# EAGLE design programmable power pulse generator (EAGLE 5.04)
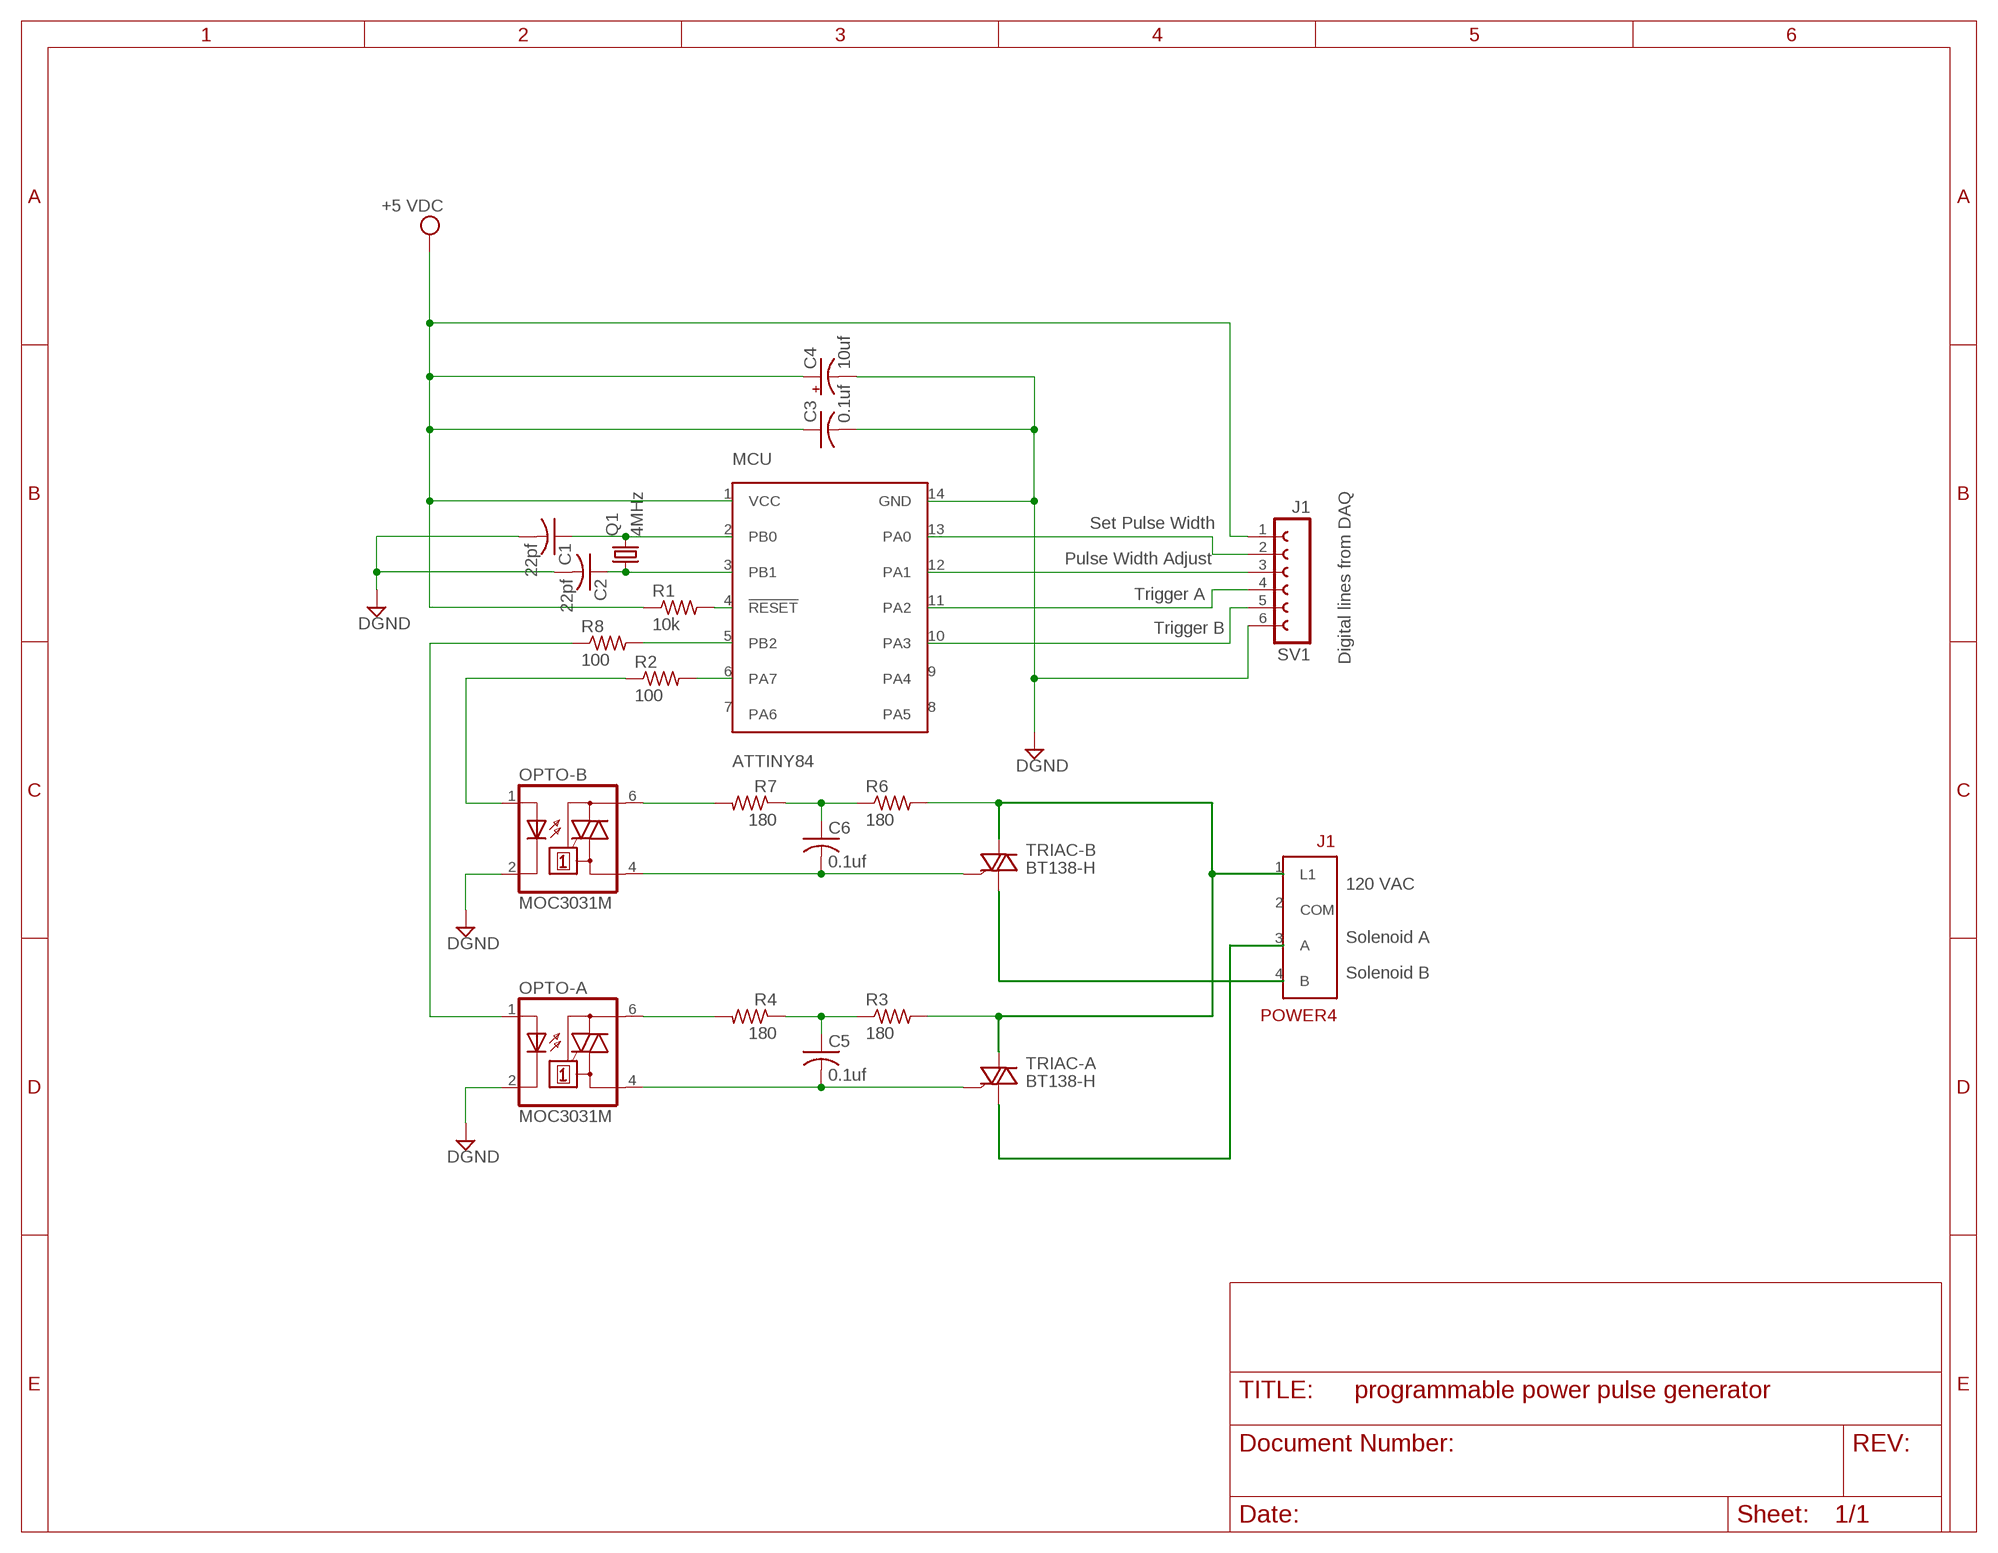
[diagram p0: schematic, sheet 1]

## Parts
C1  22pf  C-US050-035X075  [C050-035X075]
C2  22pf  C-US050-035X075  [C050-035X075]
C3  0.1uf  C-US050-035X075  [C050-035X075]
C4  10uf  CPOL-USE5-5  [E5-5]
C5  0.1uf  C-US050-035X075  [C050-035X075]
C6  0.1uf  C-US050-035X075  [C050-035X075]
J1  POWER4  [POWER4]
MCU  ATTINY84  [DIP14A]
OPTO-A  MOC3031M  [DIL06]
OPTO-B  MOC3031M  [DIL06]
Q1  4MHz  CRYSTALHC49U70  [HC49U70]
R1  10k  R-US_0204/5  [0204/5]
R2  100  R-US_0204/5  [0204/5]
R3  180  R-US_0204/5  [0204/5]
R4  180  R-US_0204/5  [0204/5]
R6  180  R-US_0204/5  [0204/5]
R7  180  R-US_0204/5  [0204/5]
R8  100  R-US_0204/5  [0204/5]
SV1  J1  FE06W  [FE06W]
TRIAC-A  BT138-H  [TO220BH]
TRIAC-B  BT138-H  [TO220BH]

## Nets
AGND: C1.2 C2.2 C3.2 C4.- MCU.14(GND) OPTO-A.2(C) OPTO-B.2(C) SV1.6 ; supply symbol labelled DGND
N$1: MCU.4(!RESET) R1.2
N$2: MCU.5(PB2) R8.2
N$3: MCU.6(PA7) R2.2
N$4: OPTO-B.1(A) R2.1
N$5: OPTO-B.6(A2) R7.2
N$6: C6.1 R6.1 R7.1
N$7: J1.1(L1) R3.2 R6.2 TRIAC-A.T2(A2) TRIAC-B.T2(A2)
N$8: MCU.13(PA0) SV1.2
N$9: C1.1 MCU.2(PB0) Q1.2
N$10: C6.2 OPTO-B.4(A1) TRIAC-B.G
N$11: MCU.12(PA1) SV1.3
N$12: J1.4(B) TRIAC-B.T1(A1)
N$13: OPTO-A.1(A) R8.1
N$14: OPTO-A.6(A2) R4.2
N$15: C5.1 R3.1 R4.1
N$16: J1.3(A) TRIAC-A.T1(A1)
N$17: C5.2 OPTO-A.4(A1) TRIAC-A.G
N$18: MCU.11(PA2) SV1.4
N$21: MCU.10(PA3) SV1.5
N$22: C2.1 MCU.3(PB1) Q1.1
VCC: C3.1 C4.+ MCU.1(VCC) R1.1 SV1.1 ; supply symbol labelled +5 VDC
Unconnected: J1.2(COM) MCU.7(PA6) MCU.8(PA5) MCU.9(PA4)

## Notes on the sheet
- Set Pulse Width
- Pulse Width Adjust
- Trigger A
- Trigger B
- Digital lines from DAQ
- 120 VAC
- Solenoid A
- Solenoid B

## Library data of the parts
C1-C3 C5 C6 = rcl:C-US: CAPACITOR, American symbol
C4 = rcl:CPOL-US: POLARIZED CAPACITOR, American symbol
J1 = trl:POWER4
MCU = trl:ATTINY84: Atmel ATTINY84 MCU, 14DIP
OPTO-A OPTO-B = optocoupler:MOC30*: 6-Pin DIP Zero-Cross Optoisolators Triac Driver Output (250/400 Volt Peak) Source: http://www.fairchildsemi.com/ds/MO/MOC3043-M.pdf
Q1 = crystal:CRYSTAL: CRYSTAL
R1-R4 R6-R8 = resistor:R-US_: RESISTOR, American symbol
SV1 = con-lsta:FE06W: FEMALE HEADER
TRIAC-A TRIAC-B = triac:BT138: TRIAC Source: http://www.semiconductors.philips.com BT138_SERIES_2.pdf

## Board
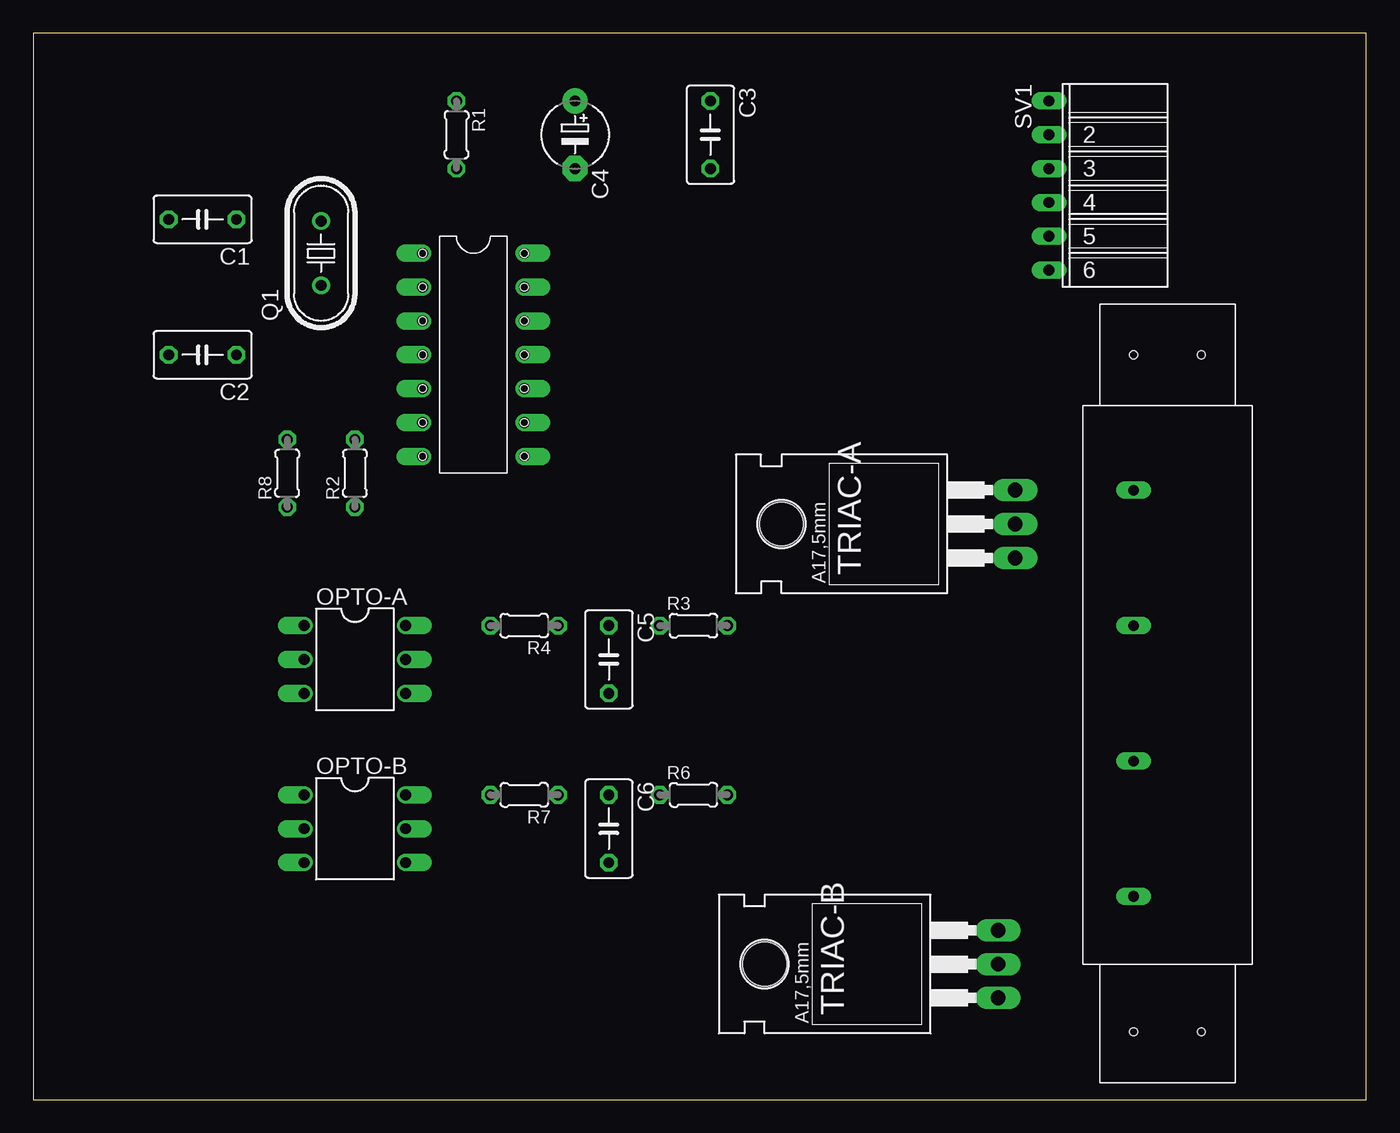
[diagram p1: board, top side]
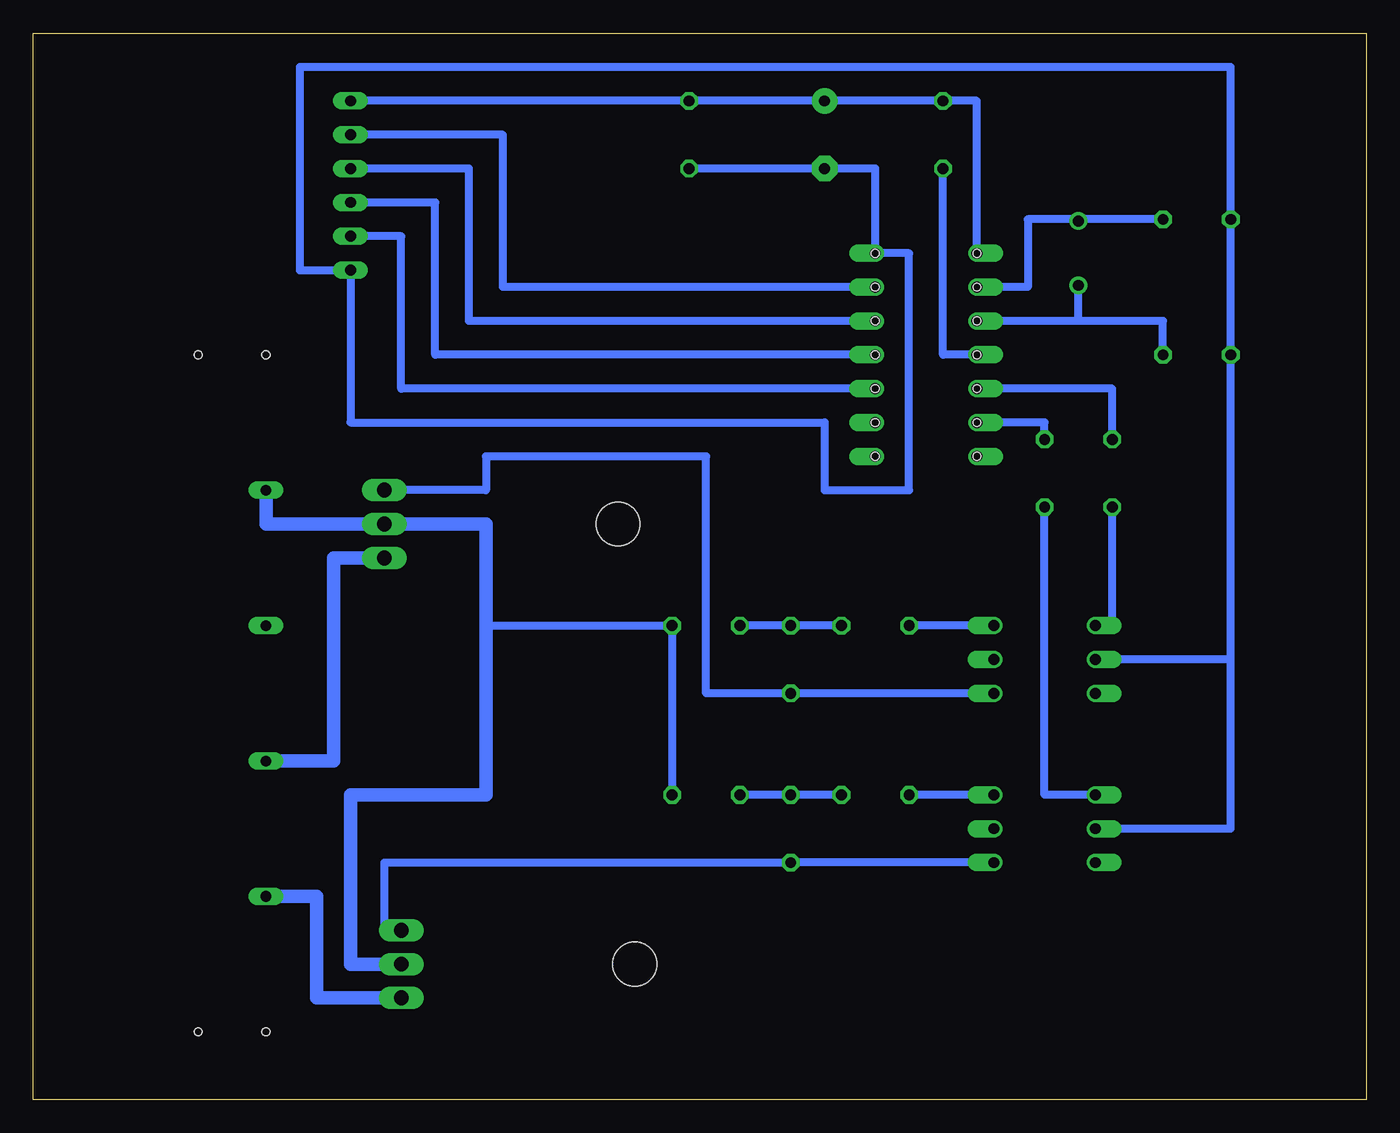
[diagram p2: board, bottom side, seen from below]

Size 100 x 80 mm. Coordinates in mm from the lower left corner, seen from the top.
Outline: 0,0 100,0 100,80 0,80 0,0
Copper layers (1*16): Top 0.035mm / dielectric 1.5mm / Bottom 0.035mm
Design rules "default": minimum track width 10mil, minimum drill 24mil, track to track 8mil, track to pad 8mil, pad to pad 8mil, via to via 8mil, smd to smd 8mil, copper to edge 40mil, drill to drill 8mil, minimum pad ring 10mil, minimum via ring 8mil, stop-mask expansion 4mil, vias tented up to drill 0mil, thermal gap 10mil

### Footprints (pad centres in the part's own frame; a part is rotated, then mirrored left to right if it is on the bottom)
C050-035X075 = drill 0.813 octagon: 1 -2.54,0; 2 2.54,0
E5-5 = drill 0.813 pad 1.905 round: + -2.54,0 | drill 0.813 pad 1.905 octagon: - 2.54,0
POWER4 = drill 0.8 long: 1 1.27,8.89; 2 1.27,-1.27; 3 1.27,-11.43; 4 1.27,-21.59 | hole 0.6: 1.27,19.05; 1.27,-31.75; 6.35,19.05; 6.35,-31.75
DIP14A = drill 0.8 offset: 1 -3.81,8.89; 2 -3.81,6.35; 3 -3.81,3.81; 4 -3.81,1.27; 5 -3.81,-1.27; 6 -3.81,-3.81; 7 -3.81,-6.35; 8 3.81,-6.35; 9 3.81,-3.81; 10 3.81,-1.27; 11 3.81,1.27; 12 3.81,3.81; 13 3.81,6.35; 14 3.81,8.89 | hole 0.6: -3.81,-6.35; -3.81,-3.81; -3.81,-1.27; -3.81,1.27; -3.81,3.81; -3.81,6.35; -3.81,8.89; 3.81,8.89; 3.81,6.35; 3.81,3.81; 3.81,1.27; 3.81,-1.27; 3.81,-3.81; 3.81,-6.35
DIL06 = drill 0.813 offset: 1 -2.54,-3.81; 2 0,-3.81; 3 2.54,-3.81; 4 2.54,3.81; 5 0,3.81; 6 -2.54,3.81
HC49U70 = drill 0.813 round: 1 -2.413,0; 2 2.413,0
0204/5 = drill 0.813 octagon: 1 -2.54,0; 2 2.54,0
FE06W = drill 0.813 long: 1 -6.35,0; 2 -3.81,0; 3 -1.27,0; 4 1.27,0; 5 3.81,0; 6 6.35,0
TO220BH = drill 1.118 long: G 2.54,-6.35; T1 -2.54,-6.35; T2 0,-6.35 | hole 3.302: 0,11.176

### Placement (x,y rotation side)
C1  12.7,66.04 180 top
C2  12.7,55.88 180 top
C3  50.8,72.39 270 top
C4  40.64,72.39 270 top
C5  43.18,33.02 270 top
C6  43.18,20.32 270 top
J1  81.28,36.83 0 top
MCU  33.02,54.61 0 top
OPTO-A  24.13,33.02 270 top
OPTO-B  24.13,20.32 270 top
Q1  21.59,63.5 90 top
R1  31.75,72.39 270 top
R2  24.13,46.99 90 top
R3  49.53,35.56 0 top
R4  36.83,35.56 180 top
R6  49.53,22.86 0 top
R7  36.83,22.86 180 top
R8  19.05,46.99 90 top
SV1  76.2,68.58 270 top
TRIAC-A  67.31,43.18 90 top
TRIAC-B  66.04,10.16 90 top

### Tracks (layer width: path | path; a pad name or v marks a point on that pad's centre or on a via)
AGND
  Bottom 0.61: C3.2 C4.- 36.83,69.85 MCU.14 34.29,63.5 34.29,45.72 40.64,45.72 40.64,50.8 76.2,50.8 SV1.6 80.01,62.23 80.01,77.47 10.16,77.47 C1.2 C2.2 10.16,33.02 | 10.16,33.02 OPTO-A.2 | OPTO-B.2 10.16,20.32 10.16,33.02
N$1
  Bottom 0.61: R1.2 31.75,55.88 MCU.4
N$2
  Bottom 0.61: R8.2 19.05,53.34 MCU.5
N$3
  Bottom 0.61: R2.2 24.13,50.8 MCU.6
N$4
  Bottom 0.61: R2.1 24.13,22.86 OPTO-B.1
N$5
  Bottom 0.61: OPTO-B.6 R7.2
N$6
  Bottom 0.61: R7.1 C6.1 R6.1
N$7
  Bottom 0.61: 66.04,35.56 R3.2 R6.2
  Bottom 1.016: J1.1 82.55,43.18 TRIAC-A.T2 66.04,43.18 66.04,35.56 66.04,22.86 76.2,22.86 76.2,10.16 TRIAC-B.T2
N$8
  Bottom 0.61: MCU.13 64.77,60.96 64.77,72.39 SV1.2
N$9
  Bottom 0.406: 21.59,66.04 Q1.2
  Bottom 0.61: C1.1 21.59,66.04 25.4,66.04 25.4,60.96 MCU.2
N$10
  Bottom 0.61: OPTO-B.4 C6.2 73.66,17.78 73.66,12.7 TRIAC-B.G
N$11
  Bottom 0.61: MCU.12 67.31,58.42 67.31,69.85 SV1.3
N$12
  Bottom 1.016: TRIAC-B.T1 78.74,7.62 78.74,15.24 J1.4
N$13
  Bottom 0.406: 19.05,40.64 19.05,39.37
  Bottom 0.61: R8.1 19.05,40.64 19.05,35.56 OPTO-A.1
N$14
  Bottom 0.61: OPTO-A.6 R4.2
N$15
  Bottom 0.61: R3.1 C5.1 R4.1
N$16
  Bottom 1.016: TRIAC-A.T1 77.47,40.64 77.47,25.4 J1.3
N$17
  Bottom 0.61: OPTO-A.4 C5.2 49.53,30.48 49.53,48.26 66.04,48.26 66.04,45.72 TRIAC-A.G
N$18
  Bottom 0.61: MCU.11 69.85,55.88 69.85,67.31 SV1.4
N$21
  Bottom 0.61: MCU.10 72.39,53.34 72.39,64.77 SV1.5
N$22
  Bottom 0.61: 21.59,58.42 MCU.3 | 21.59,58.42 Q1.1 | 21.59,58.42 15.24,58.42 C2.1
VCC
  Bottom 0.61: SV1.1 C3.1 C4.+ R1.1 29.21,74.93 MCU.1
